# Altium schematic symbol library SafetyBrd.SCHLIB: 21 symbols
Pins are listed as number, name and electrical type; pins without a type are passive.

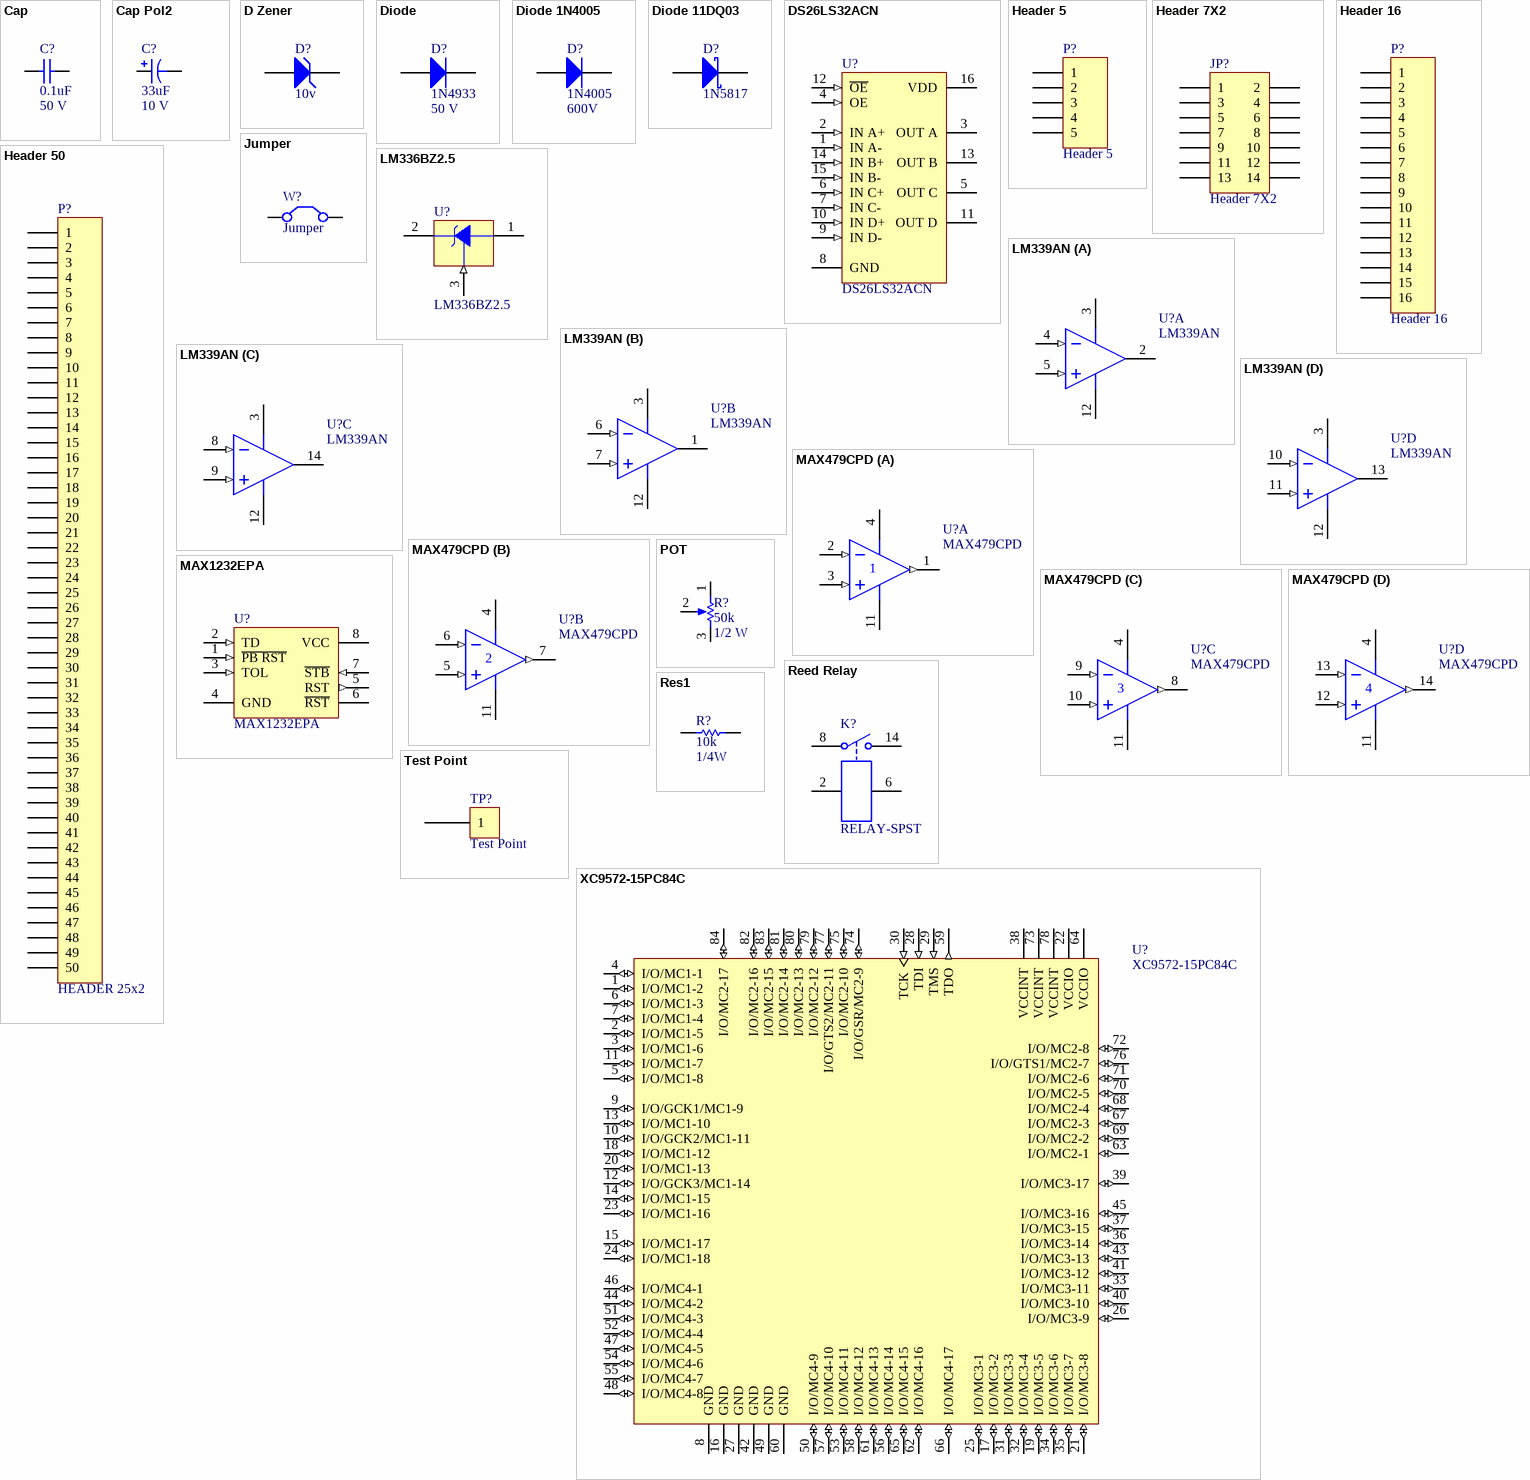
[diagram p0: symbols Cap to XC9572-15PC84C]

## Cap
designator C?, comment 0.1uF  Rating: 50 V
CAP .1UF 50V STACK METAL FILM; Part Number: 111-R166; Manufacturer: Panasonic; Manufacturer Part Number: ECQ-V1H104JL; Assumed Cost Quantity: 10; PCB Footprint: RAD-0.2; Tolerance: 0.1
footprint RAD-0.3 (Capacitor; 2 Leads)
simulation model CAP (Capacitor)
signal-integrity model Cap
footprint CAPR5.08-7.8X3.2
footprint CAPR2.54-5.1X3.2
footprint capr5.08-7.6x5
footprint capr5.08-7.6x4
pins: 1, 2

## Cap Pol2
designator C?, comment 33uF  Rating: 10 V
CAPACITOR TANT 33UF 10V 10% RAD; Part Number: 113-3361; Manufacturer: KEMET; Manufacturer Part Number: T350F336K010AS; Assumed Cost Quantity: 1; Tolerance: 0.1
footprint CAPTR2.5-0.8-6A
simulation model CAP (Capacitor)
signal-integrity model Cap Pol
footprint CAPPA14.05-10.5x6.3
footprint CAPPA23.6-18.5x8.5
footprint CAPPA31.6-26.5x12.5
footprint CAPPA35.6-30.5x18.5
footprint CAPPA46.1-41x21.5
pins: 1, 2

## D Zener
designator D?, comment 10v
DIODE ZENER 10V 500MW 5% DO-35; Part Number: 413-52400; Manufacturer: Diodes, Inc.; Manufacturer Part Number: 1N5240B-T; Assumed Cost Quantity: 1
footprint DO-35
simulation model ZENER (Diode)
signal-integrity model D Zener
pins: 1 A, 2 K

## Diode
designator D?, comment 1N4933  Rating: 50 V
RECTIFIER FST REC 50V 1A DO-41; Part Number: 410-4933; Manufacturer: Diodes, Inc.; Manufacturer Part Number: 1N4933-T; Assumed Cost Quantity: 1; PCB Footprint: DIODE-0.4
simulation model DIODE (Diode)
signal-integrity model Diode
footprint dio7.8-4.6x2 (Diode, Axial; Body 4.6 x 1.9 mm (LxDia. max), Lead Dia. 0.53 mm (max))
pins: 1 A, 2 K

## Diode 1N4005
designator D?, comment 1N4005  Rating: 600V
RECTIFIER 1 AMP 600V DO-41; Part Number: 410-4005; Manufacturer: General Semiconductor; Assumed Cost Quantity: 10; PCB Footprint: DIODE-0.4
footprint DIO10.46-5.3x2.8 (Diode, Axial; Body 5.2 x 2.7 mm (LxDia. max), Lead Dia. 0.86 mm (max))
simulation model 1N4005 (DIODE)
signal-integrity model 1N4005
pins: 1 A, 2 K

## Diode 11DQ03
designator D?, comment 1N5817
RECTIFIER SCHOTTKY 1A 20V DO-41; Part Number: 414-58174; Manufacturer: General Semiconductor; Assumed Cost Quantity: 1; PCB Footprint: SM/DO214AA_21
footprint DIO10.46-5.3x2.8 (Diode, Axial; Body 5.2 x 2.7 mm (LxDia. max), Lead Dia. 0.86 mm (max))
simulation model 11DQ03 (DIODE)
pins: 1 A, 2 K

## DS26LS32ACN
designator U?
IC LINE RCVR QUAD DIFF 16-DIP; Part Number: 324-26320; Manufacturer: National Semiconductor; PackageDocument: 2000; Assumed Cost Quantity: 1
footprint N16E (DIP; 16 Leads; Row Spacing 7.62 mm; Pitch 2.54 mm)
pins: 1 IN A- (in), 2 IN A+ (in), 3 OUT A (hiz), 4 OE (in), 5 OUT C (hiz), 6 IN C+ (in), 7 IN C- (in), 8 GND (power), 9 IN D- (in), 10 IN D+ (in), 11 OUT D (hiz), 12 ~{OE} (in), 13 OUT B (hiz), 14 IN B+ (in), 15 IN B- (in), 16 VDD (power)

## Header 5
designator P?
CONN HEADER 5POS .100 VERT TIN; Part Number: 531-53; Manufacturer: Molex/Waldom Electronics Corp.; Assumed Cost Quantity: 1; PCB Footprint: PHDR1X5
footprint HDR1X5 (Connector; Header; 5 Position)
signal-integrity model Connector
pins: 1, 2, 3, 4, 5

## Header 7X2
designator JP?
CONN HEADER 14POS 2MM VERT GOLD; Part Number: 531-141; Manufacturer: Molex/Waldom Electronics Corp.; Manufacturer Part Number: 87758-1416; Assumed Cost Quantity: 1
footprint HDR2X7-2mm
signal-integrity model Connector
pins: 1, 2, 3, 4, 5, 6, 7, 8, 9, 10, 11, 12, 13, 14

## Header 16
designator P?
CONN HEADER VERT 16POS .100 15AU; Part Number: 531-163; Manufacturer: AMP/Tyco Electronics; Manufacturer Part Number: 499922-3; Assumed Cost Quantity: 1; Value: HEADER 8X2
footprint HDR2X8-Latch
signal-integrity model Connector
pins: 1, 2, 3, 4, 5, 6, 7, 8, 9, 10, 11, 12, 13, 14, 15, 16

## Header 50
designator P?, comment HEADER 25x2
CONN HEADER VERT 50POS .100 30AU; Part Number: 531-501; Manufacturer: AMP/Tyco Electronics; Manufacturer Part Number: 1-499206-0; Assumed Cost Quantity: 1
footprint HDR2X25-Latch
pins: 1, 2, 3, 4, 5, 6, 7, 8, 9, 10, 11, 12, 13, 14, 15, 16, 17, 18, 19, 20, 21, 22, 23, 24, 25, 26, 27, 28, 29, 30, 31, 32, 33, 34, 35, 36, 37, 38, 39, 40, 41, 42, 43, 44, 45, 46, 47, 48, 49, 50

## Jumper
designator W?
CONN HEADER 2POS .100 VERT TIN; Part Number: 531-20; Manufacturer: Molex/Waldom Electronics Corp; Assumed Cost Quantity: 1; PCB Footprint: BLKCON.100/VH/TM1SQS/W.100/2
footprint RAD-0.2 (Jumper Wire; 2 Leads)
footprint JUMPER
pins: 1 C1, 2 C2

## LM336BZ2.5
designator U?
IC REFERENCE DIODE 2.5V TO-92; Part Number: 348-3360; Manufacturer: National Semiconductor; Manufacturer Part Number: LM336BZ-2.5-ND; Assumed Cost Quantity: 1; PCB Footprint: Z03A; Tolerance: 0.02
footprint Z03A (TO, Flat Index; 3 In-Line, Axial Leads; Body Dia. 4.6mm; Leads 0.53 x 0.39 mm (max))
signal-integrity model Guessed Model (IC Model Details Guessed by Setup Helper)
pins: 1 -V, 2 +V, 3 ADJ (in)

## LM339AN
designator U?
IC COMPRTR QUAD 0-70DEG C 14-DIP; Part Number: 339-3390; Manufacturer: National Semiconductor; Assumed Cost Quantity: 1; PCB Footprint: N14A
footprint N14A (DIP; 14 Leads; Row Spacing 7.62 mm; Pitch 2.54 mm)
simulation model LM339 (SUBCKT)
signal-integrity model Guessed Model (IC Model Details Guessed by Setup Helper)
pins on every part: 3 V+ (power), 12 GND (power)
part A pins: 2 OUT (oc), 4 IN- (in), 5 IN+ (in)
part B pins: 1 OUT (oc), 6 IN- (in), 7 IN+ (in)
part C pins: 8 IN- (in), 9 IN+ (in), 14 OUT (oc)
part D pins: 10 IN- (in), 11 IN+ (in), 13 OUT (oc)

## MAX479CPD
designator U?
IC OPAMP SNGL SUP QUAD 14-DIP; Part Number: 338-4790; Manufacturer: Maxim; Assumed Cost Quantity: 1
footprint PD14 (DIP; 14 Leads; Row Spacing 7.62 mm; Pitch 2.54 mm)
simulation model MAX4795 (SUBCKT)
signal-integrity model Guessed Model (IC Model Details Guessed by Setup Helper)
pins on every part: 4 V+ (power), 11 V- (power)
part A pins: 1 OUT (out), 2 IN- (in), 3 IN+ (in)
part B pins: 5 IN+ (in), 6 IN- (in), 7 OUT (out)
part C pins: 8 OUT (out), 9 IN- (in), 10 IN+ (in)
part D pins: 12 IN+ (in), 13 IN- (in), 14 OUT (out)

## MAX1232EPA
designator U?
IC MPU SUPERVISORY CIRCUIT 8-DIP; Part Number: 320-12320; Manufacturer: Maxim; Assumed Cost Quantity: 1
footprint PA8 (DIP; 8 Leads; Row Spacing 7.62 mm; Pitch 2.54 mm)
signal-integrity model Guessed Model (IC Model Details Guessed by Setup Helper)
pins: 1 ~{PB RST} (in), 2 TD (in), 3 TOL (in), 4 GND (power), 5 RST (out), 6 ~{RST} (oc), 7 ~{STB} (in), 8 VCC (power)

## POT
designator R?, comment 50k  Rating: 1/2 W
POT 50K OHM 3/8" SQ CERM SL MT; Part Number: 145-5031; Manufacturer: Bourns, Inc.; Manufacturer Part Number: 3299W-1-503; Assumed Cost Quantity: 1; Tolerance: 0.1
footprint POT
pins: 1 TOP, 2 TAP, 3 POT

## Reed Relay
designator K?, comment RELAY-SPST
RELAY REED SPST 5VDC DIP; Part Number: 546-50; Manufacturer: US Relay's & Technology; Manufacturer Part Number: D1A05A; Assumed Cost Quantity: 1
footprint Reed Dip-14
pins: 2, 6, 8, 14

## Res1
designator R?, comment 10k  Rating: 1/4W
10k ohm resistor; Part Number: 141-10020; Manufacturer: Yageo; Manufacturer Part Number: MFR-25FBF-10K0; Assumed Cost Quantity: 5; PCB Footprint: AXIAL-0.3; Tolerance: 0.01
footprint AXIAL-0.3 (Resistor; 2 Leads)
simulation model RESISTOR (Resistor)
signal-integrity model Res
pins: 1, 2
1 alternate drawing of the same symbol

## Test Point
designator TP?
TEST POINT PC MULTI PURPOSE BLK; Part Number: 535-5011; Manufacturer: Keystone Electronics; Manufacturer Part Number: 5011; Assumed Cost Quantity: 10
footprint Test Point
pins: 1

## XC9572-15PC84C
designator U?
IC CPLD 72 MACROCELL 84-PLCC; Part Number: 342-95720; Manufacturer: Xilinx; Assumed Cost Quantity: 1
footprint PC84 (84-Pin Plastic Leaded Chip Carrier (PC84))
3D model XC9572-PC84 (84-Pin Plastic Leaded Chip Carrier (PC84))
signal-integrity model XC9572_PLCC84 (XC9500)
pins: 1 I/O/MC1-2 (io), 2 I/O/MC1-5 (io), 3 I/O/MC1-6 (io), 4 I/O/MC1-1 (io), 5 I/O/MC1-8 (io), 6 I/O/MC1-3 (io), 7 I/O/MC1-4 (io), 8 GND (power), 9 I/O/GCK1/MC1-9 (io), 10 I/O/GCK2/MC1-11 (io), 11 I/O/MC1-7 (io), 12 I/O/GCK3/MC1-14 (io), 13 I/O/MC1-10 (io), 14 I/O/MC1-15 (io), 15 I/O/MC1-17 (io), 16 GND (power), 17 I/O/MC3-2 (io), 18 I/O/MC1-12 (io), 19 I/O/MC3-5 (io), 20 I/O/MC1-13 (io), 21 I/O/MC3-8 (io), 22 VCCIO (power), 23 I/O/MC1-16 (io), 24 I/O/MC1-18 (io), 25 I/O/MC3-1 (io), 26 I/O/MC3-9 (io), 27 GND (power), 28 TDI (in), 29 TMS (in), 30 TCK (in), 31 I/O/MC3-3 (io), 32 I/O/MC3-4 (io), 33 I/O/MC3-11 (io), 34 I/O/MC3-6 (io), 35 I/O/MC3-7 (io), 36 I/O/MC3-14 (io), 37 I/O/MC3-15 (io), 38 VCCINT (power), 39 I/O/MC3-17 (io), 40 I/O/MC3-10 (io), 41 I/O/MC3-12 (io), 42 GND (power), 43 I/O/MC3-13 (io), 44 I/O/MC4-2 (io), 45 I/O/MC3-16 (io), 46 I/O/MC4-1 (io), 47 I/O/MC4-5 (io), 48 I/O/MC4-8 (io), 49 GND (power), 50 I/O/MC4-9 (io), 51 I/O/MC4-3 (io), 52 I/O/MC4-4 (io), 53 I/O/MC4-11 (io), 54 I/O/MC4-6 (io), 55 I/O/MC4-7 (io), 56 I/O/MC4-14 (io), 57 I/O/MC4-10 (io), 58 I/O/MC4-12 (io), 59 TDO (out), 60 GND (power), 61 I/O/MC4-13 (io), 62 I/O/MC4-16 (io), 63 I/O/MC2-1 (io), 64 VCCIO (power), 65 I/O/MC4-15 (io), 66 I/O/MC4-17 (io), 67 I/O/MC2-3 (io), 68 I/O/MC2-4 (io), 69 I/O/MC2-2 (io), 70 I/O/MC2-5 (io), 71 I/O/MC2-6 (io), 72 I/O/MC2-8 (io), 73 VCCINT (power), 74 I/O/GSR/MC2-9 (io), 75 I/O/MC2-10 (io), 76 I/O/GTS1/MC2-7 (io), 77 I/O/GTS2/MC2-11 (io), 78 VCCINT (power), 79 I/O/MC2-12 (io), 80 I/O/MC2-13 (io), 81 I/O/MC2-14 (io), 82 I/O/MC2-16 (io), 83 I/O/MC2-15 (io), 84 I/O/MC2-17 (io)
